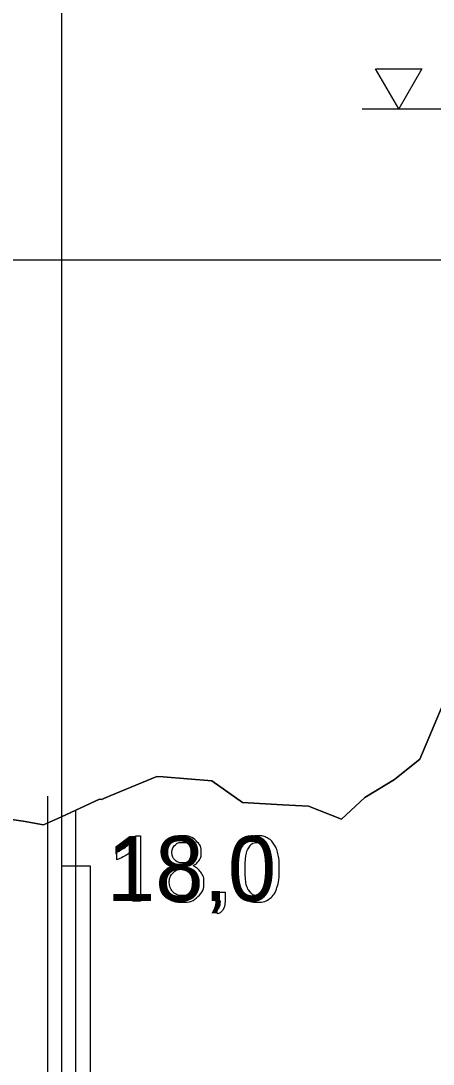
# Model space of a CAD drawing. Extents: x 700746 to 706058, y 6570320 to 6580460.
# Drawn here: x 704098.2 to 704133.7, y 6575826 to 6575915.9 of the extents above; entities that cross this region are included whole.
import ezdxf

# ---------------------------------------------------------------- set-up
doc = ezdxf.new("R2010")
doc.units = 0
for name, color, linetype in [('Default', 7, 'Continuous'), ('GEOLPUNKT', 7, 'Continuous'), ('illumineerimisjooned', 7, 'Continuous'), ('Plokid', 7, 'Continuous'), ('Täide', 7, 'Continuous'), ('VEEKOGU', 7, 'Continuous'), ('Veetase', 7, 'Continuous')]:
    doc.layers.add(name, color=color, linetype=linetype)

msp = doc.modelspace()

# ---------------------------------------------------------------- linework, layer by layer
at = {"layer": 'Default'}
msp.add_lwpolyline([(704095.808, 6575847.331), (704098.405, 6575846.937), (704100.144, 6575846.626), (704101.698, 6575847.331), (704104.989, 6575848.827), (704105.15, 6575848.803), (704105.953, 6575849.166), (704109.924, 6575850.786), (704110.453, 6575850.767), (704114.637, 6575850.405), (704117.272, 6575848.566), (704120.718, 6575848.364), (704122.951, 6575848.247), (704125.799, 6575847.127), (704127.816, 6575848.993), (704130.359, 6575850.53), (704132.549, 6575852.271), (704135.788, 6575859.966)], dxfattribs=at)
at = {"layer": 'GEOLPUNKT'}
for points in [[(704101.698, 6576033.071), (704101.698, 6575848.578)], [(704101.698, 6575848.578), (704101.698, 6575773.071)], [(704108.075, 6575845.68), (704108.518, 6575845.68), (704108.518, 6575840.059)], [(704108.518, 6575840.059), (704107.831, 6575840.059), (704107.831, 6575844.439)], [(704106.456, 6575843.61), (704106.456, 6575844.275)], [(704115.002, 6575840.059), (704115.002, 6575840.84), (704115.783, 6575840.84), (704115.783, 6575840.059)], [(704115.39, 6575840.059), (704115.002, 6575840.059)], [(704115.147, 6575838.949), (704114.955, 6575839.243)]]:
    msp.add_lwpolyline(points, dxfattribs=at)
msp.add_lwpolyline([(704104.198, 6575843.071), (704101.698, 6575843.071), (704101.698, 6575823.071), (704104.198, 6575823.071)], close=True, dxfattribs=at)
for points in [[(704106.456, 6575844.275), (704107.033, 6575844.546), (704107.464, 6575844.932), (704107.896, 6575845.317), (704108.075, 6575845.68)], [(704111.344, 6575843.098), (704110.913, 6575843.254), (704110.706, 6575843.544), (704110.499, 6575843.834), (704110.499, 6575844.238), (704110.499, 6575844.849), (704110.937, 6575845.264), (704111.376, 6575845.68), (704112.105, 6575845.68), (704112.837, 6575845.68), (704113.283, 6575845.255), (704113.73, 6575844.83), (704113.73, 6575844.219), (704113.73, 6575843.83), (704113.525, 6575843.542), (704113.32, 6575843.254), (704112.903, 6575843.098), (704113.42, 6575842.93), (704113.69, 6575842.555), (704113.96, 6575842.181), (704113.96, 6575841.661), (704113.96, 6575840.943), (704113.452, 6575840.454), (704112.945, 6575839.965), (704112.116, 6575839.965), (704111.288, 6575839.965), (704110.78, 6575840.456), (704110.272, 6575840.947), (704110.272, 6575841.68), (704110.272, 6575842.227), (704110.551, 6575842.596), (704110.829, 6575842.964), (704111.344, 6575843.098)], [(704116.803, 6575842.82), (704116.803, 6575843.813), (704117.007, 6575844.419), (704117.211, 6575845.026), (704117.614, 6575845.353), (704118.017, 6575845.68), (704118.628, 6575845.68), (704119.078, 6575845.68), (704119.419, 6575845.499), (704119.76, 6575845.317), (704119.98, 6575844.976), (704120.2, 6575844.634), (704120.326, 6575844.143), (704120.452, 6575843.653), (704120.452, 6575842.82), (704120.452, 6575841.836), (704120.25, 6575841.229), (704120.048, 6575840.623), (704119.645, 6575840.294), (704119.242, 6575839.965), (704118.628, 6575839.965), (704117.818, 6575839.965), (704117.356, 6575840.543), (704116.803, 6575841.244), (704116.803, 6575842.82)], [(704107.831, 6575844.439), (704107.583, 6575844.202), (704107.18, 6575843.965), (704106.777, 6575843.729), (704106.456, 6575843.61)], [(704111.207, 6575844.262), (704111.207, 6575843.866), (704111.46, 6575843.614), (704111.714, 6575843.362), (704112.122, 6575843.362), (704112.519, 6575843.362), (704112.77, 6575843.612), (704113.021, 6575843.862), (704113.021, 6575844.224), (704113.021, 6575844.602), (704112.762, 6575844.859), (704112.503, 6575845.117), (704112.114, 6575845.117), (704111.721, 6575845.117), (704111.464, 6575844.865), (704111.207, 6575844.613), (704111.207, 6575844.262)], [(704117.511, 6575842.82), (704117.511, 6575841.439), (704117.833, 6575840.984), (704118.155, 6575840.528), (704118.628, 6575840.528), (704119.1, 6575840.528), (704119.422, 6575840.986), (704119.744, 6575841.443), (704119.744, 6575842.82), (704119.744, 6575844.203), (704119.422, 6575844.658), (704119.101, 6575845.112), (704118.62, 6575845.112), (704118.148, 6575845.112), (704117.865, 6575844.711), (704117.511, 6575844.199), (704117.511, 6575842.82)], [(704110.981, 6575841.675), (704110.981, 6575841.381), (704111.119, 6575841.105), (704111.256, 6575840.83), (704111.531, 6575840.679), (704111.806, 6575840.528), (704112.122, 6575840.528), (704112.615, 6575840.528), (704112.933, 6575840.846), (704113.252, 6575841.163), (704113.252, 6575841.652), (704113.252, 6575842.149), (704112.924, 6575842.474), (704112.596, 6575842.799), (704112.099, 6575842.799), (704111.614, 6575842.799), (704111.297, 6575842.478), (704110.981, 6575842.157), (704110.981, 6575841.675)], [(704114.955, 6575839.243), (704115.172, 6575839.339), (704115.276, 6575839.525), (704115.379, 6575839.71), (704115.39, 6575840.059)], [(704115.783, 6575840.059), (704115.783, 6575839.626), (704115.63, 6575839.36), (704115.478, 6575839.094), (704115.147, 6575838.949)]]:
    msp.add_open_spline(points, degree=3, dxfattribs=at)
at = {"layer": 'illumineerimisjooned'}
msp.add_line((704100.539, 6575798.338), (704100.539, 6575849.105), dxfattribs=at)
at = {"layer": 'Plokid'}
msp.add_line((704102.939, 6575802.475), (704102.939, 6575847.895), dxfattribs=at)
msp.add_lwpolyline([(704102.939, 6575847.895), (704104.989, 6575848.827), (704105.15, 6575848.803), (704105.953, 6575849.166), (704109.924, 6575850.786), (704110.453, 6575850.767), (704114.637, 6575850.405), (704117.272, 6575848.566), (704120.718, 6575848.364), (704122.951, 6575848.247), (704125.799, 6575847.127), (704127.816, 6575848.993), (704130.359, 6575850.53), (704132.549, 6575852.271), (704135.788, 6575859.966), (704137.04, 6575868.411), (704137.76, 6575872.008), (704139.582, 6575877.526), (704144.49, 6575891.182), (704144.696, 6575896.33), (704145.635, 6575904.181), (704146.184, 6575910.459), (704149.793, 6575940.696)], dxfattribs=at)
at = {"layer": 'Täide'}
msp.add_lwpolyline([(704135.788, 6575859.966), (704132.549, 6575852.271), (704130.359, 6575850.53), (704127.816, 6575848.993), (704125.799, 6575847.127), (704122.951, 6575848.247), (704120.718, 6575848.364), (704117.272, 6575848.566), (704114.637, 6575850.405), (704110.453, 6575850.767), (704109.924, 6575850.786), (704105.953, 6575849.166), (704105.15, 6575848.803), (704104.989, 6575848.827), (704101.698, 6575847.331), (704100.144, 6575846.626), (704098.405, 6575846.937), (704095.808, 6575847.331)], dxfattribs=at)
at = {"layer": 'VEEKOGU'}
msp.add_line((704144.653, 6575895.271), (704079.759, 6575895.271), dxfattribs=at)
msp.add_lwpolyline([(704095.808, 6575847.331), (704098.405, 6575846.937), (704100.144, 6575846.626), (704101.698, 6575847.331), (704104.989, 6575848.827), (704105.15, 6575848.803), (704105.953, 6575849.166), (704109.924, 6575850.786), (704110.453, 6575850.767), (704114.637, 6575850.405), (704117.272, 6575848.566), (704120.718, 6575848.364), (704122.951, 6575848.247), (704125.799, 6575847.127), (704127.816, 6575848.993), (704130.359, 6575850.53), (704132.549, 6575852.271), (704135.788, 6575859.966), (704137.04, 6575868.411), (704137.76, 6575872.008), (704139.582, 6575877.526), (704144.49, 6575891.182), (704144.653, 6575895.271)], dxfattribs=at)
at = {"layer": 'Veetase'}
msp.add_line((704127.569, 6575908.291), (704176.342, 6575908.291), dxfattribs=at)
msp.add_line((704127.569, 6575908.291), (704176.342, 6575908.291), dxfattribs=at)
msp.add_lwpolyline([(704130.732, 6575911.739), (704132.723, 6575911.739), (704130.732, 6575908.291), (704128.742, 6575911.739)], close=True, dxfattribs=at)
msp.add_lwpolyline([(704130.732, 6575911.739), (704132.723, 6575911.739), (704130.732, 6575908.291), (704128.742, 6575911.739)], close=True, dxfattribs=at)

# ---------------------------------------------------------------- texts
at = {"layer": 'GEOLPUNKT'}
msp.add_text('18,0', height=5.6, dxfattribs=at).set_placement((704105.607, 6575840.059))

doc.saveas('drawing.dxf')
